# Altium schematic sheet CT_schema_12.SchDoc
size 281 x 153 mm
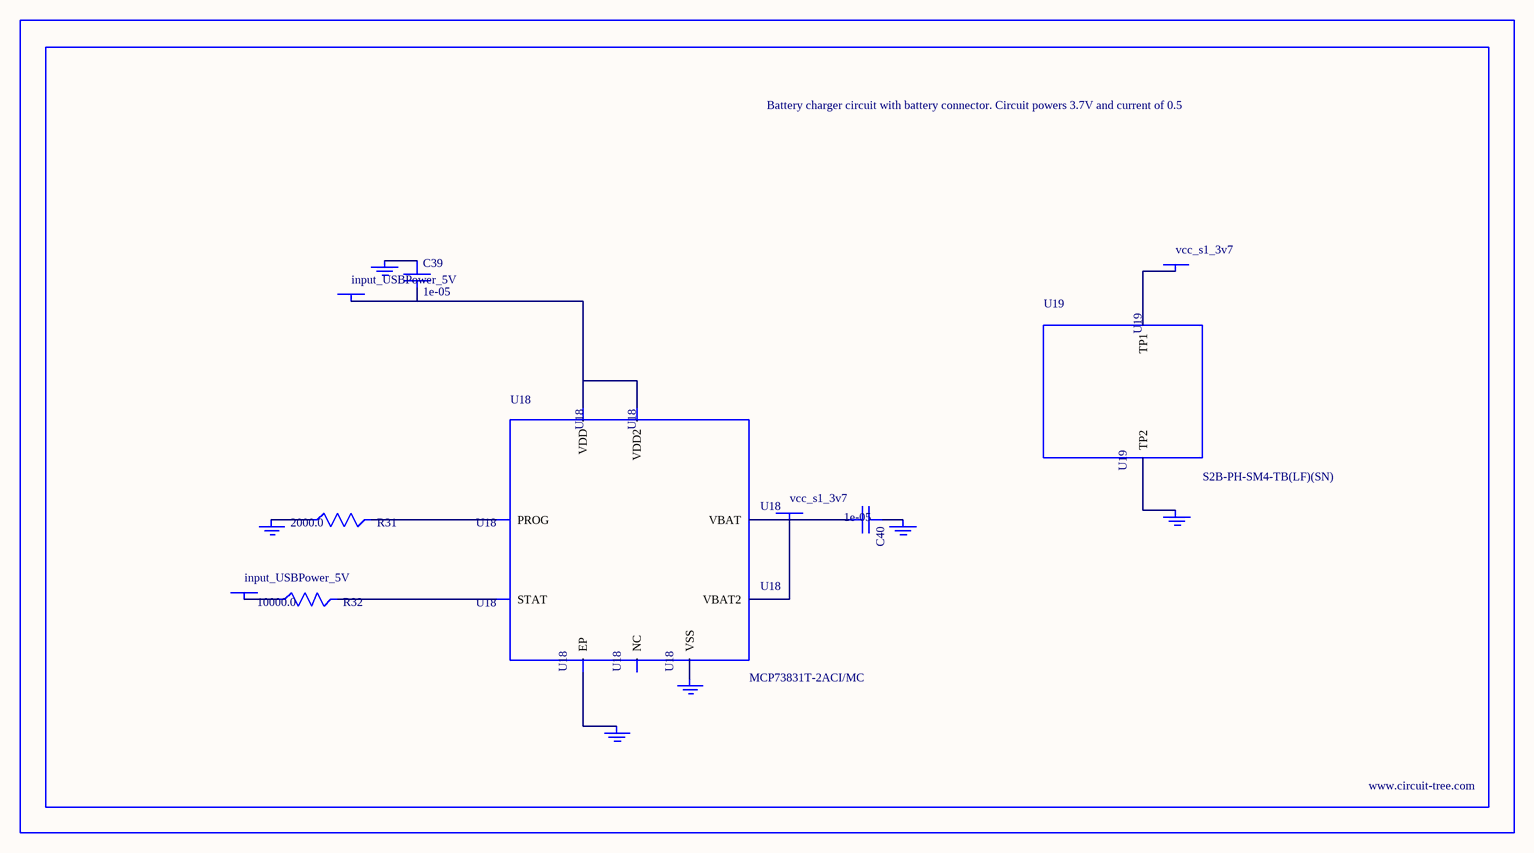
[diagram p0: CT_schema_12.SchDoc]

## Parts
BORDER11  (no value)
C39  1e-05  [C1206]
C40  1e-05  [C1206]
GND_INSTANCE_11_0  (no value)
GND_INSTANCE_11_1  (no value)
GND_INSTANCE_11_2  (no value)
GND_INSTANCE_11_3  (no value)
GND_INSTANCE_11_4  (no value)
GND_INSTANCE_11_5  (no value)
POWER_INSTANCE_11_0  input_USBPower_5V
POWER_INSTANCE_11_1  input_USBPower_5V
POWER_INSTANCE_11_2  vcc_s1_3v7
POWER_INSTANCE_11_3  vcc_s1_3v7
R31  2000.0  [R0603]
R32  10000.0  [R0603]
U18  MCP73831T-2ACI/MC  [DFN8_2X3MC]
U19  S2B-PH-SM4-TB(LF)(SN)  [JST-2-SMD]

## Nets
NetC39_1: C39.1 GND_INSTANCE_11_0.0(GND)
NetC39_2: C39.2 POWER_INSTANCE_11_0.0(PWR) U18.1(VDD) U18.2(VDD2)
NetC40_1: C40.1 GND_INSTANCE_11_1.0(GND)
NetC40_2: C40.2 POWER_INSTANCE_11_2.0(PWR) U18.3(VBAT) U18.4(VBAT2)
NetGND_INSTANCE_11_2_0: GND_INSTANCE_11_2.0(GND) R31.1
NetGND_INSTANCE_11_3_0: GND_INSTANCE_11_3.0(GND) U18.9(EP)
NetGND_INSTANCE_11_4_0: GND_INSTANCE_11_4.0(GND) U18.6(VSS)
NetGND_INSTANCE_11_5_0: GND_INSTANCE_11_5.0(GND) U19.2(TP2)
NetPOWER_INSTANCE_11_1_0: POWER_INSTANCE_11_1.0(PWR) R32.1
NetPOWER_INSTANCE_11_3_0: POWER_INSTANCE_11_3.0(PWR) U19.1(TP1)
NetR31_2: R31.2 U18.8(PROG)
NetR32_2: R32.2 U18.5(STAT)

Not connected (* = marked no-connect by the designer): U18 7(NC)

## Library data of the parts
BORDER11 = BORDER_PAGE11
C39 C40 = C1206C106K3RACTU
GND_INSTANCE_11_0-GND_INSTANCE_11_5 = GND
POWER_INSTANCE_11_0-POWER_INSTANCE_11_3 = PWR
R31 = RC0603JR-072KL
R32 = RC0603JR-0710KL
